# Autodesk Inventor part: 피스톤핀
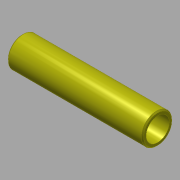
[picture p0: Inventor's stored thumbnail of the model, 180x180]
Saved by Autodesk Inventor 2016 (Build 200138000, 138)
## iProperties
Created: 2016-11
Part Number: 피스톤핀
Material: 강철, 탄소
Document SubType Name: Modeling
Designer: mduedu
Density: 7.87 g/cm^3
Mass: 24.6584 g
Surface Area: 42.7469 cm^2
Volume: 3.13322 cm^3
Appearance: 노란색
Author: mduedu
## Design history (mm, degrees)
sketch "스케치1"
  geometry: C1 r 5 at (0, 0); C2 r 6.5 at (0, 0); 1 further point
  constraints: 2 centre point, 2 coincident
  dimensions: "d0" = 10 diameter of C1; "d1" = 13 diameter of C2
extrude "돌출1" new body sketch "스케치1" stored distance "d2" = 58; taper "d3" = 0 deg
chamfer "모따기1" distance "d4" = 0.5; stored, may be unused: second distance "d5" = 2, angle "d6" = 45 deg
node "솔리드1"
